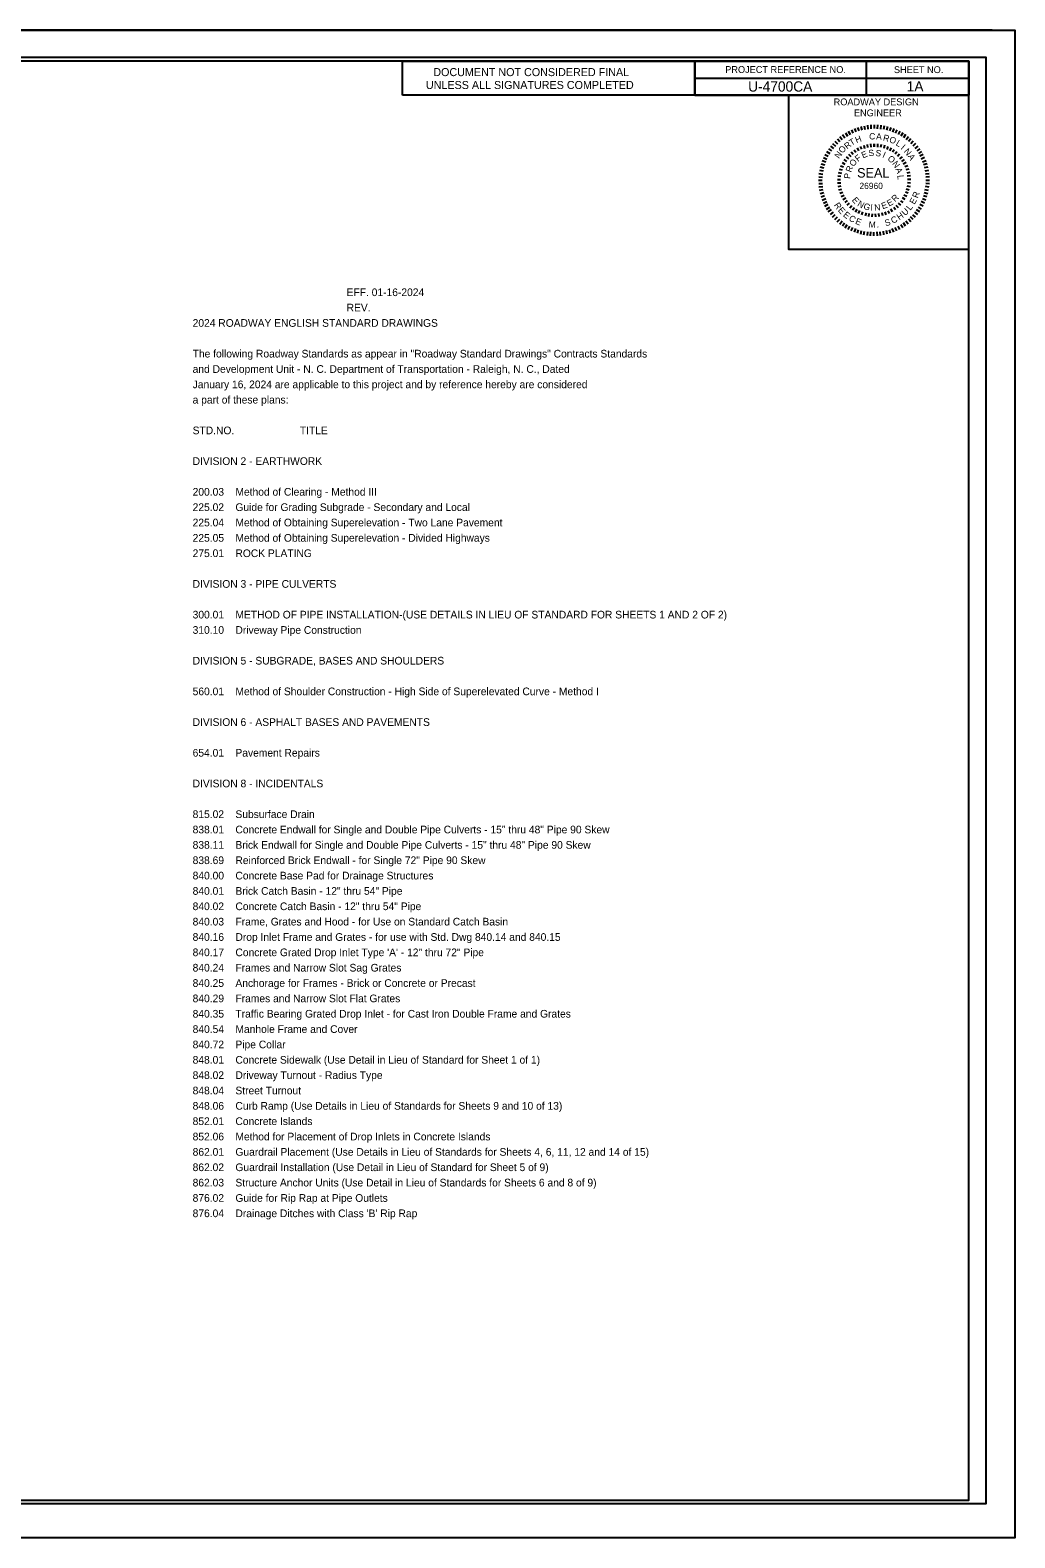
# Model space of a CAD drawing. Extents: x 573687 to 576329, y -53413 to -52265.
# Drawn here: x 574668 to 575387, y -53365 to -52265 of the extents above; entities that cross this region are included whole.
import ezdxf

# ---------------------------------------------------------------- set-up
doc = ezdxf.new("R2010")
doc.units = 0
for name, color, linetype in [('Default', 7, 'Continuous'), ('Sheet Cutting Line CELL', 7, 'Continuous'), ('Sheet Data Field CELL', 7, 'Continuous'), ('Sheet Data Text CELL', 7, 'Continuous'), ('Sheet Plan CELL', 7, 'Continuous'), ('Sheet Plot Border Inside CELL', 7, 'Continuous'), ('Sheet Plot Border Outside CELL', 7, 'Continuous'), ('Sheet Sticker Exception Certification CELL', 7, 'Continuous')]:
    doc.layers.add(name, color=color, linetype=linetype)

msp = doc.modelspace()

# ---------------------------------------------------------------- linework, layer by layer
at = {"layer": 'Default'}
for p, q in [((575267.4, -52337.5), (575268.5, -52340)), ((575269.7, -52336.6), (575270.6, -52339.1)), ((575272, -52335.8), (575272.8, -52338.4)), ((575274.3, -52335.1), (575275, -52337.8)), ((575276.7, -52334.6), (575277.2, -52337.3)), ((575279.1, -52334.2), (575279.5, -52337)), ((575281.6, -52334), (575281.7, -52336.8)), ((575284, -52333.9), (575284, -52336.7)), ((575286.5, -52334), (575286.3, -52336.8)), ((575288.9, -52334.2), (575288.6, -52337)), ((575291.3, -52334.6), (575290.8, -52337.3)), ((575293.7, -52335.1), (575293.1, -52337.8)), ((575296.1, -52335.8), (575295.2, -52338.4)), ((575298.4, -52336.6), (575297.4, -52339.2)), ((575300.6, -52337.5), (575299.5, -52340)), ((575253.7, -52347.6), (575255.8, -52349.4)), ((575255.4, -52345.8), (575257.3, -52347.7)), ((575257.2, -52344.1), (575259, -52346.2)), ((575259, -52342.5), (575260.7, -52344.7)), ((575261, -52341.1), (575262.6, -52343.4)), ((575263.1, -52339.8), (575264.5, -52342.1)), ((575265.2, -52338.6), (575266.5, -52341)), ((575276.4, -52348.9), (575277, -52351.1)), ((575278.9, -52348.2), (575279.3, -52350.5)), ((575281.4, -52347.9), (575281.7, -52350.2)), ((575284, -52347.7), (575284, -52350)), ((575284, -52350), (575284, -52347.7)), ((575286.6, -52347.9), (575286.4, -52350.2)), ((575289.1, -52348.2), (575288.7, -52350.5)), ((575291.6, -52348.9), (575291, -52351.1)), ((575302.8, -52338.6), (575301.6, -52341)), ((575305, -52339.8), (575303.5, -52342.2)), ((575307, -52341.1), (575305.5, -52343.4)), ((575309, -52342.6), (575307.3, -52344.8)), ((575310.9, -52344.1), (575309, -52346.2)), ((575312.6, -52345.8), (575310.7, -52347.8)), ((575314.3, -52347.6), (575312.3, -52349.4)), ((575247.1, -52357.8), (575249.6, -52358.9)), ((575248.1, -52355.6), (575250.6, -52356.9)), ((575249.3, -52353.5), (575251.7, -52354.9)), ((575250.7, -52351.4), (575252.9, -52353)), ((575252.1, -52349.4), (575254.3, -52351.1)), ((575262, -52359.3), (575263.9, -52360.6)), ((575263.6, -52357.2), (575265.4, -52358.7)), ((575265.4, -52355.3), (575267, -52357)), ((575267.3, -52353.6), (575268.7, -52355.4)), ((575269.4, -52352.1), (575270.6, -52354)), ((575271.6, -52350.8), (575272.7, -52352.8)), ((575273.9, -52349.7), (575274.8, -52351.8)), ((575294.1, -52349.7), (575293.2, -52351.9)), ((575296.4, -52350.8), (575295.3, -52352.8)), ((575298.6, -52352.1), (575297.4, -52354)), ((575300.7, -52353.6), (575299.3, -52355.4)), ((575302.6, -52355.4), (575301, -52357)), ((575304.4, -52357.2), (575302.6, -52358.7)), ((575306, -52359.3), (575304.1, -52360.6)), ((575315.9, -52349.5), (575313.7, -52351.2)), ((575317.3, -52351.5), (575315.1, -52353)), ((575318.7, -52353.5), (575316.3, -52354.9)), ((575319.9, -52355.6), (575317.4, -52356.9)), ((575320.9, -52357.9), (575318.4, -52359)), ((575243.8, -52369.5), (575246.5, -52369.9)), ((575244.2, -52367.1), (575246.9, -52367.6)), ((575244.7, -52364.7), (575247.3, -52365.4)), ((575245.3, -52362.4), (575248, -52363.2)), ((575246.1, -52360), (575248.7, -52361)), ((575257.9, -52368.7), (575260.2, -52369.2)), ((575258.6, -52366.2), (575260.8, -52366.9)), ((575259.5, -52363.8), (575261.6, -52364.7)), ((575260.7, -52361.4), (575262.7, -52362.6)), ((575307.3, -52361.5), (575305.3, -52362.6)), ((575308.5, -52363.8), (575306.4, -52364.7)), ((575309.4, -52366.2), (575307.2, -52366.9)), ((575310.1, -52368.7), (575307.8, -52369.2)), ((575321.9, -52360.1), (575319.3, -52361.1)), ((575322.7, -52362.4), (575320, -52363.2)), ((575323.3, -52364.8), (575320.6, -52365.4)), ((575323.8, -52367.2), (575321.1, -52367.7)), ((575324.2, -52369.6), (575321.5, -52369.9)), ((575243.5, -52374.4), (575246.2, -52374.4)), ((575243.6, -52372), (575246.3, -52372.1)), ((575243.6, -52376.8), (575246.3, -52376.7)), ((575243.8, -52379.3), (575246.5, -52379)), ((575244.1, -52381.7), (575246.9, -52381.2)), ((575257.3, -52373.8), (575259.6, -52373.8)), ((575257.4, -52376.3), (575259.7, -52376.2)), ((575257.5, -52371.2), (575259.8, -52371.5)), ((575257.7, -52378.9), (575259.9, -52378.5)), ((575258.2, -52381.4), (575260.4, -52380.8)), ((575309.7, -52381.5), (575307.5, -52380.9)), ((575308, -52378.5), (575310.3, -52378.9)), ((575310.5, -52371.2), (575308.2, -52371.5)), ((575310.6, -52376.4), (575308.3, -52376.2)), ((575310.7, -52373.8), (575308.4, -52373.9)), ((575323.8, -52381.8), (575321.1, -52381.3)), ((575324.2, -52379.4), (575321.4, -52379)), ((575324.4, -52372), (575321.7, -52372.2)), ((575324.5, -52374.5), (575321.7, -52374.5)), ((575324.4, -52376.9), (575321.7, -52376.8)), ((575244.7, -52384.1), (575247.3, -52383.4)), ((575245.3, -52386.5), (575247.9, -52385.6)), ((575246.1, -52388.8), (575248.7, -52387.8)), ((575247, -52391), (575249.6, -52389.9)), ((575248.1, -52393.2), (575250.6, -52391.9)), ((575259, -52383.9), (575261.2, -52383.1)), ((575260, -52386.2), (575262.1, -52385.2)), ((575261.3, -52388.5), (575263.3, -52387.3)), ((575262.8, -52390.6), (575264.6, -52389.2)), ((575264.4, -52392.6), (575266.1, -52391)), ((575266.3, -52394.4), (575267.8, -52392.7)), ((575301.7, -52394.4), (575300.1, -52392.7)), ((575303.5, -52392.6), (575301.8, -52391.1)), ((575305.2, -52390.7), (575303.4, -52389.3)), ((575306.6, -52388.5), (575304.7, -52387.3)), ((575307.9, -52386.3), (575305.8, -52385.3)), ((575308.9, -52383.9), (575306.8, -52383.1)), ((575319.8, -52393.3), (575317.4, -52392)), ((575320.9, -52391.1), (575318.4, -52390)), ((575321.8, -52388.8), (575319.3, -52387.9)), ((575322.6, -52386.5), (575320, -52385.7)), ((575323.3, -52384.2), (575320.6, -52383.5)), ((575249.3, -52395.4), (575251.7, -52393.9)), ((575250.6, -52397.4), (575252.9, -52395.8)), ((575252.1, -52399.4), (575254.3, -52397.7)), ((575253.6, -52401.3), (575255.7, -52399.4)), ((575255.3, -52403), (575257.3, -52401.1)), ((575257.1, -52404.7), (575258.9, -52402.7)), ((575268.3, -52396), (575269.6, -52394.2)), ((575270.4, -52397.4), (575271.6, -52395.4)), ((575272.7, -52398.6), (575273.7, -52396.5)), ((575275.1, -52399.6), (575275.9, -52397.4)), ((575278.1, -52398.1), (575277.6, -52400.3)), ((575280.1, -52400.8), (575280.4, -52398.6)), ((575282.7, -52401.1), (575282.8, -52398.8)), ((575285.2, -52401.1), (575285.1, -52398.8)), ((575287.8, -52400.9), (575287.5, -52398.6)), ((575290.3, -52400.4), (575289.8, -52398.1)), ((575292.8, -52399.6), (575292.1, -52397.5)), ((575295.2, -52398.7), (575294.2, -52396.6)), ((575297.5, -52397.5), (575296.3, -52395.5)), ((575299.7, -52396), (575298.3, -52394.2)), ((575310.8, -52404.8), (575309, -52402.7)), ((575312.6, -52403.1), (575310.6, -52401.1)), ((575314.3, -52401.3), (575312.2, -52399.5)), ((575315.8, -52399.4), (575313.7, -52397.7)), ((575317.3, -52397.5), (575315, -52395.9)), ((575318.6, -52395.4), (575316.3, -52394)), ((575259, -52406.3), (575260.7, -52404.1)), ((575260.9, -52407.7), (575262.5, -52405.5)), ((575263, -52409.1), (575264.4, -52406.7)), ((575265.1, -52410.3), (575266.4, -52407.8)), ((575267.3, -52411.4), (575268.5, -52408.8)), ((575269.6, -52412.3), (575270.6, -52409.7)), ((575271.9, -52413.1), (575272.7, -52410.5)), ((575274.3, -52413.8), (575274.9, -52411.1)), ((575276.6, -52414.3), (575277.1, -52411.6)), ((575279.1, -52414.6), (575279.4, -52411.9)), ((575281.5, -52414.9), (575281.7, -52412.1)), ((575283.9, -52414.9), (575283.9, -52412.2)), ((575286.4, -52414.9), (575286.2, -52412.1)), ((575288.8, -52414.6), (575288.5, -52411.9)), ((575291.2, -52414.3), (575290.8, -52411.6)), ((575293.6, -52413.8), (575293, -52411.1)), ((575296, -52413.1), (575295.2, -52410.5)), ((575298.3, -52412.3), (575297.3, -52409.7)), ((575300.6, -52411.4), (575299.4, -52408.9)), ((575302.8, -52410.3), (575301.5, -52407.9)), ((575304.9, -52409.1), (575303.5, -52406.8)), ((575307, -52407.8), (575305.4, -52405.5)), ((575308.9, -52406.3), (575307.2, -52404.2))]:
    msp.add_line(p, q, dxfattribs=at)
at = {"layer": 'Sheet Cutting Line CELL'}
msp.add_line((575370.2, -52264.9), (573686.7, -52264.9), dxfattribs=at)
at = {"layer": 'Sheet Plan CELL'}
for p, q in [((575278.2, -52287.4), (575278.2, -52312.4)), ((575153.2, -52299.9), (575353.2, -52299.9)), ((575153.2, -52312.4), (575353.2, -52312.4)), ((575153.2, -52312.4), (575353.2, -52312.4))]:
    msp.add_line(p, q, dxfattribs=at)
for points in [[(575353.2, -52287.4), (573853.2, -52287.4), (573853.2, -53337.4), (575353.2, -53337.4)], [(575153.2, -52287.4), (575353.2, -52287.4), (575353.2, -52312.4), (575153.2, -52312.4)]]:
    msp.add_lwpolyline(points, close=True, dxfattribs=at)
msp.add_lwpolyline([(575353.2, -52424.9), (575221.8, -52424.9), (575221.8, -52312.4), (575353.2, -52312.4)], dxfattribs=at)
at = {"layer": 'Sheet Plot Border Inside CELL'}
msp.add_lwpolyline([(573699.7, -53339.9), (575365.7, -53339.9), (575365.7, -52284.9), (573699.7, -52284.9)], close=True, dxfattribs=at)
at = {"layer": 'Sheet Plot Border Outside CELL'}
msp.add_lwpolyline([(573686.7, -52264.9), (575386.7, -52264.9), (575386.7, -53364.9), (573686.7, -53364.9)], close=True, dxfattribs=at)
at = {"layer": 'Sheet Sticker Exception Certification CELL'}
for p, q in [((574939.9, -52312.4), (574939.9, -52287.4)), ((574939.9, -52287.4), (575153.2, -52287.4)), ((575153.2, -52287.4), (575153.2, -52312.4)), ((575153.2, -52312.4), (574939.9, -52312.4))]:
    msp.add_line(p, q, dxfattribs=at)

# ---------------------------------------------------------------- texts
at = {"layer": 'Default'}
for s, height, rotation, p in [('R', 4.6, 38.6075, (575264.4, -52352)), ('T', 4.6, 30.4466, (575267.5, -52349.4)), ('H', 4.6, 21.0146, (575271.2, -52347.4)), ('C', 4.6, 357.3039, (575280.3, -52344.5)), ('A', 4.6, 357.3039, (575285.4, -52344.6)), ('R', 4.6, 345.2946, (575290.2, -52345.3)), ('O', 4.6, 342.2378, (575294.7, -52346.6)), ('L', 4.6, 329.1015, (575299.4, -52348.6)), ('I', 4.6, 319.5261, (575303.1, -52351.3)), ('N', 4.6, 53.6237, (575258.4, -52359)), ('O', 4.6, 51.6643, (575261.1, -52355.1)), ('O', 4.6, 53.4838, (575269.1, -52364.8)), ('F', 4.6, 38.1876, (575272.2, -52361.1)), ('E', 4.6, 22.8914, (575275.9, -52358.5)), ('S', 4.6, 7.5951, (575280.2, -52357)), ('S', 4.6, 352.2989, (575284.8, -52356.6)), ('I', 4.6, 337.0026, (575289.7, -52357.6)), ('O', 4.6, 321.7064, (575293.4, -52359.4)), ('N', 4.6, 310.2316, (575305.4, -52353.5)), ('A', 4.6, 300.4641, (575308.4, -52356.9)), ('P', 4.6, 84.0763, (575266.6, -52373.5)), ('R', 4.6, 68.7801, (575267.3, -52369)), ('SEAL', 6.9, 359.947, (575271.6, -52372.4)), ('N', 4.6, 306.4101, (575296.9, -52362.4)), ('A', 4.6, 291.1139, (575299.4, -52366.2)), ('L', 4.6, 275.8176, (575300.9, -52370.8)), ('26960', 4.6, 359.947, (575273.3, -52380.8)), ('R', 4.6, 303.882, (575254.5, -52392.5)), ('E', 4.6, 310.0171, (575267.5, -52389)), ('N', 4.6, 330.8721, (575271.4, -52392.9)), ('G', 4.6, 339.6384, (575275.8, -52395)), ('I', 4.6, 357.7332, (575281.3, -52396.5)), ('N', 4.6, 5.3628, (575284.4, -52396.7)), ('E', 4.6, 20.7549, (575290.3, -52395.6)), ('E', 4.6, 30.7408, (575295, -52393.7)), ('R', 4.6, 44.5119, (575299.4, -52390.5)), ('L', 4.6, 52.154, (575310.5, -52396.7)), ('E', 4.6, 60.9466, (575313.5, -52392.4)), ('R', 4.6, 69.6194, (575315.9, -52387.8)), ('E', 4.6, 311.9538, (575257.3, -52396.5)), ('E', 4.6, 320.5966, (575261, -52400.3)), ('C', 4.6, 329.2691, (575265.1, -52403.4)), ('E', 4.6, 338.2416, (575269.9, -52406)), ('S', 4.6, 16.5636, (575292.5, -52408)), ('C', 4.6, 25.5662, (575297.6, -52406.2)), ('H', 4.6, 34.3888, (575302.4, -52403.7)), ('U', 4.6, 43.2714, (575306.6, -52400.6)), ('M', 4.6, 356.0369, (575279.9, -52408.8)), ('.', 4.6, 3.7793, (575285.9, -52408.9))]:
    msp.add_text(s, height=height, rotation=rotation, dxfattribs=at).set_placement(p)
at = {"layer": 'Sheet Data Field CELL'}
for s, p in [('U-4700CA', (575192.1, -52309.7)), ('1A ', (575307.8, -52309.6))]:
    msp.add_text(s, height=7.5, dxfattribs=at).set_placement(p)
at = {"layer": 'Sheet Data Text CELL'}
for s, p in [('                                                      EFF. 01-16-2024', (574786.8, -52458.9)), ('                                                      REV. ', (574786.8, -52470.1)), ('2024 ROADWAY ENGLISH STANDARD DRAWINGS', (574786.8, -52481.3)), ('The following Roadway Standards as appear in "Roadway Standard Drawings" Contracts Standards ', (574786.8, -52503.7)), ('and Development Unit - N. C. Department of Transportation - Raleigh, N. C., Dated ', (574786.8, -52514.9)), ('January 16, 2024 are applicable to this project and by reference hereby are considered ', (574786.8, -52526.1)), ('a part of these plans:', (574786.8, -52537.3)), ('STD.NO.                       TITLE', (574786.8, -52559.7)), ('DIVISION 2 - EARTHWORK', (574786.8, -52582.1)), ('200.03    Method of Clearing - Method III', (574786.8, -52604.5)), ('225.02    Guide for Grading Subgrade - Secondary and Local', (574786.8, -52615.7)), ('225.04    Method of Obtaining Superelevation - Two Lane Pavement', (574786.8, -52626.9)), ('225.05    Method of Obtaining Superelevation - Divided Highways', (574786.8, -52638.1)), ('275.01    ROCK PLATING', (574786.8, -52649.3)), ('DIVISION 3 - PIPE CULVERTS', (574786.8, -52671.7)), ('300.01    METHOD OF PIPE INSTALLATION-(USE DETAILS IN LIEU OF STANDARD FOR SHEETS 1 AND 2 OF 2) ', (574786.8, -52694.1)), ('310.10    Driveway Pipe Construction', (574786.8, -52705.3)), ('DIVISION 5 - SUBGRADE, BASES AND SHOULDERS', (574786.8, -52727.7)), ('560.01    Method of Shoulder Construction - High Side of Superelevated Curve - Method I', (574786.8, -52750.1)), ('DIVISION 6 - ASPHALT BASES AND PAVEMENTS', (574786.8, -52772.5)), ('654.01    Pavement Repairs', (574786.8, -52794.9)), ('DIVISION 8 - INCIDENTALS', (574786.8, -52817.3)), ('815.02    Subsurface Drain', (574786.8, -52839.7)), ('838.01    Concrete Endwall for Single and Double Pipe Culverts - 15" thru 48" Pipe 90 Skew', (574786.8, -52850.9)), ('838.11    Brick Endwall for Single and Double Pipe Culverts - 15" thru 48" Pipe 90 Skew', (574786.8, -52862.1)), ('838.69    Reinforced Brick Endwall - for Single 72" Pipe 90 Skew', (574786.8, -52873.3)), ('840.00    Concrete Base Pad for Drainage Structures', (574786.8, -52884.5)), ('840.01    Brick Catch Basin - 12" thru 54" Pipe', (574786.8, -52895.7)), ('840.02    Concrete Catch Basin - 12" thru 54" Pipe', (574786.8, -52906.9)), ('840.03    Frame, Grates and Hood - for Use on Standard Catch Basin', (574786.8, -52918.1)), ('840.16    Drop Inlet Frame and Grates - for use with Std. Dwg 840.14 and 840.15', (574786.8, -52929.3)), ('840.17    Concrete Grated Drop Inlet Type \'A\' - 12" thru 72" Pipe', (574786.8, -52940.5)), ('840.24    Frames and Narrow Slot Sag Grates', (574786.8, -52951.7)), ('840.25    Anchorage for Frames - Brick or Concrete or Precast', (574786.8, -52962.9)), ('840.29    Frames and Narrow Slot Flat Grates', (574786.8, -52974.1)), ('840.35    Traffic Bearing Grated Drop Inlet - for Cast Iron Double Frame and Grates', (574786.8, -52985.3)), ('840.54    Manhole Frame and Cover', (574786.8, -52996.5)), ('840.72    Pipe Collar', (574786.8, -53007.7)), ('848.01    Concrete Sidewalk (Use Detail in Lieu of Standard for Sheet 1 of 1)', (574786.8, -53018.9)), ('848.02    Driveway Turnout - Radius Type', (574786.8, -53030.1)), ('848.04    Street Turnout', (574786.8, -53041.3)), ('848.06    Curb Ramp (Use Details in Lieu of Standards for Sheets 9 and 10 of 13)', (574786.8, -53052.5)), ('852.01    Concrete Islands', (574786.8, -53063.7)), ('852.06    Method for Placement of Drop Inlets in Concrete Islands', (574786.8, -53074.9)), ('862.01    Guardrail Placement (Use Details in Lieu of Standards for Sheets 4, 6, 11, 12 and 14 of 15)', (574786.8, -53086.1)), ('862.02    Guardrail Installation (Use Detail in Lieu of Standard for Sheet 5 of 9)', (574786.8, -53097.3)), ('862.03    Structure Anchor Units (Use Detail in Lieu of Standards for Sheets 6 and 8 of 9)', (574786.8, -53108.5)), ('876.02    Guide for Rip Rap at Pipe Outlets', (574786.8, -53119.7)), ("876.04    Drainage Ditches with Class 'B' Rip Rap", (574786.8, -53130.9))]:
    msp.add_text(s, height=5.6, dxfattribs=at).set_placement(p)
at = {"layer": 'Sheet Plan CELL'}
for s, p in [('PROJECT REFERENCE NO.', (575175.4, -52296.1)), ('SHEET NO.', (575298.5, -52296.2)), ('ROADWAY DESIGN', (575254.5, -52319.7)), ('ENGINEER', (575269.3, -52327.7))]:
    msp.add_text(s, height=5, dxfattribs=at).set_placement(p)
at = {"layer": 'Sheet Sticker Exception Certification CELL'}
for s, p in [('DOCUMENT NOT CONSIDERED FINAL', (574962.4, -52298.4)), ('UNLESS ALL SIGNATURES COMPLETED', (574957, -52307.8))]:
    msp.add_text(s, height=5.863, dxfattribs=at).set_placement(p)

doc.saveas('drawing.dxf')
